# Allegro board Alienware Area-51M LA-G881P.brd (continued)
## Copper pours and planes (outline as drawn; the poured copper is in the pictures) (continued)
UG2_ISL95338_1 on BOTTOM (solid shape): 126.11,143.65 126.11,142.78 126.16,142.73 126.16,142.64 126.27,142.53 126.27,142.1 126.39,141.98 126.39,141.76 126.24,141.61 125.81,141.61 125.77,141.65 125.77,141.81 125.77,141.82 125.77,142.03 125.77,142.03 125.77,142.53 125.87,142.63 125.87,143.62 125.94,143.69 126.07,143.69
UG2_ISL95338_1 on IN4 (solid shape): 122.96,128.17 122.96,127.28 122.9,127.21 120.74,127.21 120.61,127.34 120.61,128.15 120.78,128.32 122.81,128.32
UG2_ISL95338_1 on IN4 (solid shape): 126.58,142.52 126.58,142.11 127.25,141.44 127.25,141.22 126.98,140.94 126.38,140.94 125.82,141.5 125.82,142.55 126,142.73 126.37,142.73
UG2_ISL95338_2 on TOP (solid shape): 147.09,129.44 147.09,128.48 146.96,128.36 146.01,128.36 145.82,128.55 145.82,129.37 146.07,129.63 146.9,129.63
UG2_ISL95338_2 on BOTTOM (solid shape): 148.48,141.1 148.48,140.23 148.54,140.17 148.54,140.11 148.68,139.97 148.68,139.73 148.95,139.46 148.95,139.14 148.87,139.06 148.55,139.06 148.22,139.39 148.22,139.96 148.26,140 148.26,141.1 148.32,141.16 148.42,141.16
UG2_ISL95338_2 on IN4 (solid shape): 146.97,130.38 146.97,128.74 146.65,128.42 145.95,128.42 145.82,128.55 145.82,130.33 145.95,130.45 146.9,130.45
UG2_ISL95338_2 on IN4 (solid shape): 149.88,138.9 149.88,138.33 149.63,138.07 149.31,138.07 148.49,138.9 148.49,139.34 148.11,139.72 148.11,139.91 148.3,140.1 148.68,140.1
UG_3V on TOP (solid shape): 314.5,45.31 314.5,44.5 314.35,44.35 313.56,44.35 313.38,44.52 313.38,45.24 313.59,45.44 314.38,45.44
UG_3V on TOP (solid shape): 327.91,40.33 328.24,40.33 328.32,40.26 328.32,39.52 328.27,39.47 327.96,39.47 327.02,40.41 327.02,40.51 327.25,40.74 327.51,40.74
UG_3V on IN1 (solid shape): 315.29,45.49 315.29,44.65 315.01,44.37 313.82,44.37 313.46,44.73 313.46,45.59 313.54,45.67 315.11,45.67
UG_3V on IN1 (solid shape): 328.14,40.71 328.14,40.21 327.79,39.85 327.43,39.85 325.65,41.63 325.65,41.81 325.86,42.01 326.85,42.01
UG_5V on TOP (solid shape): 317.65,35.46 317.65,34.57 317.55,34.47 316.84,34.47 316.64,34.67 316.64,35.41 316.79,35.56 317.55,35.56
UG_5V on TOP (solid shape): 328.32,37.18 328.32,36.4 327.71,35.79 327.25,35.79 327.13,35.91 327.13,36.07 328.09,37.03 328.09,37.13 328.17,37.21 328.29,37.21
UG_5V on IN1 (solid shape): 318.52,35.35 318.52,34.49 318.36,34.34 317.4,34.34 317.21,34.53 317.21,35.41 317.34,35.53 318.34,35.53
UG_5V on IN1 (solid shape): 328.07,36.47 328.07,36.35 326.62,34.9 326.41,34.9 326.06,35.25 326.06,35.81 326.39,36.14 326.92,36.14 327.46,36.68 327.86,36.68
UG_+1VALWP on TOP (solid shape): 266.37,10.18 266.37,9.95 265.84,9.42 265.65,9.42 265.4,9.68 264.63,9.68 264.57,9.74 264.57,9.93 264.64,10 265.65,10 265.96,10.31 266.24,10.31
UG_+1VALWP on IN1 (solid shape): 266.34,11.48 266.34,9.95 265.79,9.4 265.68,9.4 265.48,9.6 265.48,11.48 265.66,11.66 266.17,11.66
UG_+1VALWP on IN1 (solid shape): 269.21,18.82 269.21,18.31 269.06,18.16 266.95,18.16 266.75,18.36 266.75,18.87 266.93,19.05 268.99,19.05
UG_+1VALWP on TOP: 268.3,19.28 269.16,19.28 269.26,19.17 269.26,18.41 269.14,18.29 268.25,18.29 268.1,18.44 268.1,19.07
UG_CHG on TOP (solid shape): 205.45,139.02 205.45,138.9 205.38,138.83 204.56,138.83 204.37,138.64 204.37,138.39 203.92,137.95 203.61,137.95 203.54,138.01 203.54,138.26 204.37,139.09 205.38,139.09
UG_CHG on BOTTOM (solid shape): 201.08,142.85 201.08,139.96 202.64,138.4 203.68,138.4 204.11,138.83 204.3,138.83 204.43,138.71 204.43,137.8 203.92,137.29 202.15,137.29 199.81,139.63 199.81,142.83 199.94,142.96 200.97,142.96
UG_CHG_R on BOTTOM (solid shape): 200.5,153.76 200.5,152.23 200.31,152.04 199.23,152.04 199.1,152.17 199.1,153.82 199.23,153.95 200.31,153.95
UG_CHG_R on BOTTOM (solid shape): 200.97,146.05 200.97,143.8 200.9,143.72 200.02,143.72 199.9,143.85 199.9,146.07 199.96,146.14 200.89,146.14
UG_CHG_R on IN1 (solid shape): 200.94,146.64 200.94,144.99 200.69,144.74 200.18,144.74 199.93,144.99 199.93,146.64 200.18,146.9 200.69,146.9
UG_CHG_R on IN1 (solid shape): 200.94,153.57 200.94,152.42 200.75,152.23 199.39,152.23 199.07,152.55 199.07,153.63 199.32,153.88 200.63,153.88
UG_VCCSA on IN4 (solid shape): 132.79,114.83 132.79,114.17 132.61,113.99 132.41,113.99 131.14,115.26 131.14,115.49 131.42,115.77 131.85,115.77
UG_VCCSA on IN4 (solid shape): 139.06,116.36 139.06,115.29 138.86,115.09 138.1,115.09 137.95,115.24 137.95,116.3 138.12,116.48 138.94,116.48
UG_VCCSA on BOTTOM: 138.12,117.3 138.79,117.3 139.04,117.04 139.04,116.25 138.86,116.08 138.18,116.08 137.97,116.28 137.97,117.14
UG_VCCSA on BOTTOM: 130.4,115.85 131.42,115.85 132.1,115.16 132.1,114.93 132,114.83 131.77,114.83 131.04,115.57 130.4,115.57 130.3,115.67 130.3,115.75
VCIN_ BATT_TEMP on TOP: 76.39,11.87 76.9,11.87 77.39,11.38 78.36,11.38 78.46,11.28 78.46,10.64 78.22,10.41 78.22,7.17 78.01,6.96 77.05,6.96 76.88,7.13 76.88,10.1 76.33,10.66 76.33,11.81
VDOP_CHG on TOP: 201.42,140.13 202.79,140.13 203.13,140.46 203.5,140.46 203.59,140.38 204.29,140.38 204.39,140.28 205.36,140.28 205.43,140.21 205.43,140.18 205.31,140.05 203.4,140.05 202.74,139.39 201.37,139.39 201.29,139.47 201.29,140
VSB_N_002 on BOTTOM (solid shape): 58.44,22.22 58.44,21.64 58.52,21.56 60.05,21.56 60.2,21.41 60.2,20.9 60.05,20.75 58.65,20.75 58.39,20.5 58.39,19.48 58.19,19.28 57.71,19.28 57.58,19.4 57.58,20.29 57.81,20.52 57.81,22.17 57.89,22.25 58.42,22.25
N16550351 on TOP (solid shape): 195.86,151.53 195.86,148.3 198.02,146.14 198.02,141.68 197.75,141.41 197.75,139.41 197.64,139.3 196.4,139.3 196.4,142.68 195.63,142.68 195.63,139.3 194.95,139.3 193.38,137.73 193.38,134.14 193.26,134.01 191.79,134.01 191.67,134.14 191.67,138.96 191.99,139.28 191.99,142.26 192.18,142.45 193.19,142.45 193.64,142.9 193.64,144.68 193,145.31 190.78,145.31 189.89,146.2 189.89,151.72 190.33,152.17 195.22,152.17
N16606246 on TOP (solid shape): outline of 103 points within 130,129.83 140.28,143.89
N16606246 on BOTTOM (solid shape): 132.71,143.84 133.96,143.84 135.79,142.01 137.44,142.01 137.92,141.53 137.92,136.45 137.38,135.91 137.38,129.89 136.49,129 132.45,129 132.36,129.1 132.36,135.3 131.94,135.72 129.27,135.72 129.22,136.05 128.91,136.19 128.91,138.22 129.06,138.36 129.82,138.36 130,138.54 130,142.28 130.27,142.55 130.27,143.96 130.43,144.12 132.44,144.12
N16611457 on TOP: 118.33,150.58 118.79,150.12 118.79,145.03 118.36,144.6 109.07,144.6 108.04,145.63 105.56,145.63 105.31,145.88 105.31,148.42 105.5,148.61 107.91,148.61 108.42,149.12 108.42,153.02 107.93,153.5 107.93,155.31 108.25,155.62 111.21,155.62 111.38,155.45 111.38,153.73 111.8,153.31 111.8,149.55 111.84,149.51 113.16,149.51 114.23,150.58
N16611457 on BOTTOM: 116.33,155.22 117.25,155.22 119.4,153.06 119.4,146.33 119.21,146.14 109.31,146.14 108.43,145.26 105.69,145.26 105.56,145.39 105.56,152.17 110.01,156.61 114.93,156.61
N16639315 on BOTTOM (solid shape): outline of 179 points within 112.55,168.08 116.25,172.27
N16690790 on TOP (solid shape): 205.48,159.77 205.48,156.07 205.47,156.07 205.47,154.67 205.22,154.41 201.88,154.41 201.44,154.85 201.44,157.66 201.21,157.89 194.73,157.89 194.53,157.69 194.53,155.34 192.17,152.99 185.38,152.99 185.25,153.12 185.25,155.9 185.53,156.18 188.45,156.18 192.27,160 205.24,160
N16690790 on BOTTOM (solid shape): 205.37,159.94 205.37,154.94 204.91,154.48 199.95,154.48 199.81,154.62 199.81,157.66 199.56,157.92 194.03,157.92 193.9,157.79 193.9,155.32 193.66,155.08 190.59,155.08 190.43,155.24 190.43,158.56 192.35,160.47 204.84,160.47
N16690790 on IN2 (solid shape): 205.46,160.1 205.46,154.72 205.22,154.48 200.16,154.48 200.03,154.6 200.03,156.86 199.59,157.3 194.24,157.3 193.9,156.97 193.9,155.32 193.66,155.08 191.88,155.08 191.61,155.35 191.61,159.76 192.32,160.47 205.09,160.47
N16690790 on IN3 (solid shape): 205.46,160.1 205.46,154.72 205.22,154.48 200.16,154.48 200.03,154.6 200.03,156.86 199.59,157.3 194.24,157.3 193.9,156.97 193.9,155.32 193.66,155.08 191.88,155.08 191.61,155.35 191.61,159.76 192.32,160.47 205.09,160.47
N16716198 on TOP (solid shape): 206.02,131.32 206.02,128.62 205.64,128.24 204.77,128.24 204.39,128.62 204.39,130.15 204.22,130.33 204.22,131.37 204.34,131.49 205.84,131.49
N16781018 on TOP (solid shape): 135.43,122.09 135.43,120.72 136,120.15 139.98,120.15 140.1,120.04 140.1,118.36 139.81,118.07 134.89,118.07 134.62,118.35 134.62,122.08 134.64,122.11 135.41,122.11
N16781018 on BOTTOM: 135.6,120.06 137.82,120.06 138.07,120.32 138.07,121.44 138.18,121.54 140.26,121.54 140.56,121.23 140.56,116.84 140.48,116.76 139.72,116.76 139.45,117.04 139.45,117.38 139.02,117.8 138.07,117.8 137.92,117.96 135.79,117.96 135.35,118.4 135.35,119.81
N16782292 on BOTTOM (solid shape): 148.93,122.17 148.93,119.59 148.87,119.53 147.57,119.53 147.45,119.66 147.45,120.29 147.79,120.64 147.79,122.18 147.88,122.27 148.83,122.27
N16829365 on TOP: 77.15,14.17 76.31,14.17 76.19,14.05 76.19,12.96 77.23,11.91 79.31,11.91 79.41,12.02 79.41,12.87 79.36,12.92 78.8,12.92 78.67,12.8 77.83,12.8 77.53,13.1 77.53,13.78
N16862697 on TOP: 108.48,33.11 110.07,33.11 110.2,32.98 110.2,30.95 109.88,30.63 109.05,30.63 108.8,30.88 108.8,31.65 108.42,32.03 108.42,33.04
N16862746 on BOTTOM: 100.55,35.08 101.18,35.08 101.24,35.01 101.24,32.98 101.18,32.92 100.55,32.92 100.48,32.98 100.48,35.01
N16862747 on BOTTOM: 102.01,35.14 102.83,35.14 102.89,35.2 104.16,35.2 104.29,35.08 104.29,34.95 104.23,34.88 103.53,34.88 103.15,34.5 102.96,34.5 102.64,34.19 101.94,34.19 101.88,34.25 101.88,35.01
N16862749 on BOTTOM: 101.94,34.06 102.77,34.06 102.96,34.25 104.16,34.25 104.29,34.12 104.29,33.93 104.23,33.87 103.4,33.87 103.28,33.74 102.96,33.74 102.64,33.42 102.64,32.98 102.58,32.92 101.94,32.92 101.88,32.98 101.88,34
N16862811 on BOTTOM: 100.55,26.06 101.18,26.06 101.24,25.99 101.24,24.03 101.18,23.96 100.55,23.96 100.48,24.03 100.48,25.99
N16862814 on BOTTOM: 101.94,24.85 102.51,24.85 102.76,25.1 102.76,25.18 102.94,25.36 103.22,25.36 103.34,25.23 104.42,25.23 104.48,25.17 104.48,24.98 104.42,24.92 103.47,24.92 102.77,24.22 102.77,24.09 102.64,23.96 101.94,23.96 101.88,24.03 101.88,24.79
N16862815 on BOTTOM: 101.94,26.12 102.64,26.12 102.77,26.25 104.48,26.25 104.55,26.19 104.55,25.99 104.48,25.93 103.66,25.93 103.24,25.51 102.92,25.51 102.58,25.17 101.94,25.17 101.88,25.23 101.88,26.06
N16868041 on BOTTOM: 116.23,65.87 116.93,65.87 117.06,65.75 117.06,63.27 116.67,62.89 113.94,62.89 113.88,62.95 113.88,63.9 114.01,64.03 115.66,64.03 116.17,64.54 116.17,65.81
N16868085 on BOTTOM (solid shape): 104.8,62.13 104.8,59.97 104.74,59.9 104.16,59.9 104.04,60.03 104.04,62.13 104.1,62.19 104.74,62.19
N16868091 on BOTTOM (solid shape): 106.9,60.73 107.72,60.73 107.78,60.67 107.78,60.48 107.72,60.41 106.39,60.41 106.2,60.22 106.2,60.03 106.13,59.97 105.5,59.97 105.43,60.03 105.43,60.86 105.5,60.92 106.7,60.92
N16868093 on BOTTOM (solid shape): 106.64,61.75 107.66,61.75 107.78,61.62 107.78,61.43 107.72,61.36 106.39,61.36 106.2,61.17 105.56,61.17 105.5,61.24 105.5,62.13 105.56,62.19 106.2,62.19
N16872727 on TOP: 118.26,77.68 119.28,77.68 119.4,77.56 119.4,75.91 119.15,75.65 117.56,75.65 117.44,75.78 117.44,76.86
N16872751 on BOTTOM (solid shape): 106.68,73.84 106.68,71.75 106.63,71.7 105.99,71.7 105.92,71.78 105.92,73.81 105.99,73.89 106.63,73.89
N16872754 on BOTTOM (solid shape): 108.31,72.36 108.69,72.36 109.12,71.93 109.8,71.93 109.88,71.85 109.88,71.7 109.8,71.63 108.84,71.63 108.58,71.37 108.58,71 108.37,70.79 108.09,70.79 107.31,71.56 107.31,72.57 107.37,72.62 108.05,72.62
N16872755 on BOTTOM (solid shape): 109.02,72.92 109.83,72.92 109.91,72.85 109.91,72.72 109.8,72.62 108.38,72.62 108.05,72.95 107.37,72.95 107.29,73.02 107.29,73.76 107.42,73.89 108.05,73.89
N16876699 on TOP: 107.4,41.11 108.04,41.11 108.23,41.3 110.01,41.3 110.2,41.11 110.2,40.22 110.01,40.03 107.4,40.03 107.28,40.16 107.28,40.98
N16876717 on BOTTOM: 101.37,44.92 101.5,44.79 101.5,42.89 101.37,42.76 100.74,42.76 100.61,42.89 100.61,43.81 99.82,44.6 99.82,44.84 99.89,44.92
N16876720 on BOTTOM: 102.13,43.71 103.15,43.71 103.4,43.46 104.29,43.46 104.36,43.39 104.36,43.2 104.29,43.14 103.09,43.14 102.7,42.76 102.07,42.76 102.01,42.82 102.01,43.58
N16876721 on BOTTOM: 102.07,44.92 102.89,44.92 103.4,44.41 104.23,44.41 104.29,44.35 104.29,44.22 104.23,44.16 103.02,44.16 102.89,44.03 102.07,44.03 102.01,44.09 102.01,44.85
N16876814 on BOTTOM: 114.45,54.82 113.18,53.55 111.4,53.55 111.34,53.62 111.34,54.44 111.47,54.57 113.25,54.57 113.63,54.95 113.63,56.66 113.79,56.83 114.33,56.83 114.45,56.71
N16876832 on BOTTOM: 102.32,53.68 102.83,53.68 102.96,53.55 102.96,51.59 102.89,51.52 102.32,51.52 102.2,51.65 102.2,53.55
N16876835 on BOTTOM: 103.66,52.41 104.29,52.41 104.86,51.84 105.63,51.84 105.75,51.71 105.75,51.52 105.69,51.46 103.66,51.46 103.59,51.52 103.59,52.35
N16876836 on BOTTOM: 103.66,53.68 104.29,53.68 104.36,53.62 104.36,53.3 104.8,52.86 105.69,52.86 105.82,52.73 105.82,52.54 105.75,52.47 104.48,52.47 104.29,52.66 103.72,52.66 103.59,52.79 103.59,53.62
N16880234 on BOTTOM: 161,17.87 161.57,17.87 162.33,17.1 162.33,14.95 162.2,14.82 161.31,14.82 161.19,14.95 161.19,16.66 160.87,16.98 160.87,17.74
N16880256 on BOTTOM: 136.11,15.2 138.14,15.2 138.26,15.07 138.26,14.25 138.14,14.12 137.44,14.12 137.18,13.87 137.18,13.42 137.12,13.36 136.11,13.36 135.98,13.49 135.98,15.07
N16880500 on BOTTOM: 145.64,12.09 147.7,12.09 147.8,11.99 147.8,11.4 147.75,11.35 145.64,11.35 145.59,11.4 145.59,12.04
N16884080 on BOTTOM: 125.5,11.9 127.53,11.9 127.6,11.83 127.6,11.26 127.47,11.14 125.5,11.14 125.37,11.26 125.37,11.77
N16884081 on BOTTOM: 127.66,14.76 127.85,14.76 127.91,14.69 127.91,13.87 127.72,13.68 127.72,12.79 127.53,12.6 126.71,12.6 126.64,12.66 126.64,13.23 126.9,13.49 127.15,13.49 127.6,13.93 127.6,14.69
N16884082 on BOTTOM: 126.71,14.69 126.83,14.69 126.9,14.63 126.9,13.8 126.39,13.29 126.39,12.66 126.33,12.6 125.44,12.6 125.37,12.66 125.37,13.36 125.56,13.55 126.2,13.55 126.58,13.93 126.58,14.56
N17623308 on TOP (solid shape): 202.43,165.4 202.43,162.66 202.28,162.51 201.72,162.51 201.51,162.71 201.51,165.33 201.79,165.61 202.23,165.61
N17623308 on TOP (solid shape): 206.29,165.4 206.29,162.66 206.14,162.51 205.58,162.51 205.38,162.71 205.38,165.33 205.66,165.61 206.09,165.61
N17623308 on TOP (solid shape): 210.07,165.4 210.07,162.66 209.92,162.51 209.36,162.51 209.16,162.71 209.16,165.33 209.44,165.61 209.87,165.61
N17623308 on TOP (solid shape): 198.64,165.4 198.64,162.66 198.49,162.51 198.06,162.51 197.95,162.62 197.95,162.98 197.73,163.19 197.73,165.33 198.01,165.61 198.44,165.61
N17623308 on BOTTOM: 198.09,164.23 209.29,164.23 209.92,163.6 209.92,162.53 209.69,162.3 197.2,162.3 197.13,162.38 197.13,163.27
N20453798 on TOP: 151.68,148.25 151.68,147.14 151.89,146.93 152.97,146.93 153.16,147.12 153.16,147.62 153.39,147.85 153.9,147.85 153.97,147.92 153.97,148.42 153.89,148.49 152.61,148.49 152.46,148.34 151.77,148.34
N20466818 on TOP (solid shape): 114.02,140.51 114.02,138.71 113.84,138.53 113.08,138.53 112.92,138.69 112.92,139.02 112.29,139.65 112.29,140.54 112.37,140.61 113.92,140.61
N20469265 on TOP (solid shape): 150.95,138.63 151.99,138.63 152.07,138.55 152.07,137.95 151.94,137.82 150.49,137.82 150.16,137.49 149,137.49 148.92,137.56 148.92,138.94 149.15,139.16 150.42,139.16
N20478252 on BOTTOM: 240.25,15.01 240.25,14.37 240.37,14.25 240.37,12.53 240.5,12.41 241.2,12.41 241.52,12.72 241.52,13.8 242.02,14.31 242.28,14.31 242.34,14.37 242.34,15.01 242.15,15.2 240.44,15.2
N20591895 on BOTTOM: 375.62,49.46 377.15,49.46 378.54,50.84 378.54,53.17 378.71,53.34 379.21,53.34 379.39,53.17 379.39,48.41 378.8,47.83 376.94,47.83 376.15,48.63 375.58,48.63 375.49,48.71 375.49,49.33
N20980290 on TOP: 171.08,167.68 171.03,167.62 171.03,166.63 171.19,166.46 172.03,166.46 172.29,166.2 172.29,165.31 172.35,165.25 172.49,165.25 172.57,165.32 172.57,166.15 172.65,166.23 173.21,166.23 173.29,166.32 173.29,166.5 173.5,166.71 173.5,167.64 173.47,167.68
N20994075 on TOP: 163.53,162.67 164.19,162.67 164.72,162.14 164.72,161.08 164.89,160.91 165.98,160.91 166.11,161.03 166.11,164.14 166.06,164.19 165.1,164.19 165.03,164.12 165.03,163.13 164.85,162.95 164.26,162.95 164.21,163 163.53,163 163.46,162.94 163.46,162.74
N21000962 on TOP (solid shape): 193.23,163.41 193.23,162.33 193.49,162.07 193.8,162.07 193.98,162.25 193.98,162.98 194.06,163.06 194.22,163.06 194.3,162.98 194.3,161.72 193.61,161.04 192.08,161.04 192.03,161.09 192.03,163.44 192.07,163.48 193.16,163.48
N22717170 on TOP: 156.14,149.47 156.96,149.47 157.38,149.88 159.06,149.88 160.48,151.31 161.37,151.31 161.38,151.3 161.82,151.3 161.88,151.37 161.88,152.15 161.73,152.29 159.47,152.29 158.56,153.2 158.56,154.54 158.29,154.81 157.4,154.81 157.21,154.62 157.21,151.1 157.11,151 156.19,151 156.09,150.9 156.09,149.52
N22744293 on BOTTOM: 145.38,162.08 143.74,162.08 142.04,160.38 142.04,159.45 142.28,159.2 142.99,159.2 143.38,158.81 144.94,158.81 145.72,159.59 146.96,159.59 147.23,159.86 147.23,161.43 146.99,161.67 145.79,161.67
N22932271 on TOP: 123.78,152.85 124.6,152.85 125.58,153.83 125.58,154.66 125.5,154.74 124.93,154.74 124.43,154.24 123.77,154.24 123.66,154.13 123.66,152.97
N22943835 on BOTTOM: 147.94,167.48 147.94,166.84 148.07,166.7 149.75,166.7 149.81,166.76 149.81,168.41 149.67,168.54 148.79,168.54 148.73,168.48 148.73,167.71 148.57,167.55 148.01,167.55
N22957086 on BOTTOM: 148.95,170.76 148.95,170.05 149.05,169.95 150.95,169.95 151.01,170.01 151.01,170.79 150.93,170.87 149.06,170.87
N22958603 on BOTTOM (solid shape): 129.29,131.81 129.29,130.65 129.1,130.46 127.41,130.46 127.02,130.07 126.4,130.07 126.3,130.17 126.3,131.49 126.41,131.6 128.2,131.6 128.54,131.94 129.16,131.94
N24139767 on TOP (solid shape): 268.13,69.73 268.13,68.17 268.04,67.97 268.13,67.76 268.13,64.97 267.79,64.64 267.79,64.24 268.61,63.42 268.84,63.42 268.88,63.41 269.05,63.24 269.24,63.24 269.34,63.14 269.34,62.88 269.34,62.87 269.22,62.85 269.13,62.79 269.02,62.79 269.02,62.82 268.82,63.01 268.78,63.01 268.77,63.02 268.45,63.02 267.23,64.24 267.23,67.57 266.6,68.2 266.6,69.81 266.65,69.86 268,69.86
N24654525 on TOP: 276.7,86.23 273.74,86.23 273.59,86.38 273.59,87.27 274.03,87.27 274.1,87.34 274.1,88.67 274.03,88.73 273.71,88.73 273.59,88.86 273.59,89.3 274.41,90.13 276.06,90.13 276.76,89.43 276.76,88.42 277.02,88.16 277.02,86.55
N25473625 on BOTTOM: 86.51,18.82 86.51,18.18 86.77,17.93 88.61,17.93 89.31,17.23 90.19,17.23 90.39,17.42 90.39,18.57 90.19,18.76 88.99,18.76 88.86,18.88 86.58,18.88
N25489388 on BOTTOM: 164.48,176.56 164.48,174.43 164.69,174.22 165.8,174.22 165.92,174.34 165.92,177.23 165.57,177.57 164.37,177.57 164.24,177.44 164.24,176.81
N28714782 on BOTTOM: 190.66,152.3 190.66,154.61 190.73,154.68 192.65,154.68 192.86,154.46 192.86,152.3 192.68,152.12 190.84,152.12
N28714793 on TOP (solid shape): 193.26,144.23 193.26,143.03 193.13,142.9 192.18,142.9 191.99,143.09 191.99,144.23 192.18,144.42 193.06,144.42
N28714793 on TOP (solid shape): 202.84,136.99 202.84,135.91 202.72,135.78 201.61,135.78 201.54,135.84 201.54,136.96 201.64,137.06 202.78,137.06
N28714793 on BOTTOM (solid shape): 193.27,144.57 193.27,142.95 193.22,142.9 192.24,142.9 192.05,143.09 192.05,144.1 192.05,144.11 192.05,144.62 192.13,144.69 193.14,144.69
N28714793 on IN1 (solid shape): 202.84,136.93 202.84,136.17 202.65,135.98 201.45,135.98 201.32,136.1 201.32,136.87 201.45,136.99 202.78,136.99
N28714793 on IN1: 191.6,144.42 191.6,142.07 191.86,141.82 193.13,141.82 193.32,142.01 193.32,144.36 193.13,144.55 191.73,144.55
N38701284 on TOP (solid shape): 355.96,30.91 355.96,28.7 355.7,28.45 355.7,26.36 355.02,25.68 354.15,25.68 353.97,25.86 353.97,26.97 354.2,27.2 354.38,27.2 354.66,27.48 354.66,28.01 354.66,28.02 354.66,28.35 355.65,29.34 355.65,30.88 355.71,30.94 355.93,30.94

Small or netless copper shapes (teardrops, artwork), in the pictures only: 118 on TOP, 29 on BOTTOM

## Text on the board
Ref Des/Silkscreen Bottom: H42 | H70 | H63 | H60 | H56 | H58 | H59 | H57 | SSD-2(PCle+SATA) | 4 | 2 | 3 | 1 | DDR4 ONLY - DIMM4 | DDR4 ONLY - DIMM2 | DDR4 ONLY - DIMM3 | DDR4 ONLY - DIMM1 | DIMM1->DIMM2->DIMM3->DIMM4 | Memory population order
User.Comments: CR_BGA_96P_1 | CR_GPU_1 | LA-G881P | Minjia_Cai | 2019-11-19 | 2018-11-19 | DDQ70 | 1.0(A00)
Ref Des/Silkscreen Top: B | JDGFF2 | JDGFF1 | A
GND4: GND4
COMPVAL_TYPE_TOP: L7 | L8 | GND2 | BOT
User.40: trace Width | Width/space | L4/L7 | L7/L9 | L2/L4 | L2 | L9 | 6.8mil | 8.8 mil | 8.5mil | 5.3mil | 5.3 mil | 6.9 mil | 4.8 mil | 5.9mil | 6.2mil | 4.4 mil | 3.3 mil | 4.1mil | 4.4mil | 6.2 / 4 | 6.5 / 4.5 | 5.8 /4 | 6.8 / 4 | 3.3 / 3.3 | 4.4 / 4.3 | 4.7 / 7.3 | 4 / 8 | 3.3 / 12 | 3.5 / 9 | 1_6mm-10L(PP1080,PP2116,PP7628x3)_180420.pdf | L1-TOP | L2-GND1 | L3-IN1 | L4-GND2 | L5-IN2 | L6-IN3 | L7-GND3 | L8-IN4 | L9-GND4 | L10-BOT | LAYER | NAME | STACKUP:10 LAYER | 34 ohm | 40 ohm | THICKNESS=1.6mm | 42 ohm | 50 ohm | 66 ohm | 68 ohm | 85 ohm | 90 ohm | 100 ohm | Ref
User.45: FIGURE | SIZE | 8.0 | 20.0 | 28.0 | 30.0 | 35.0 | 36.0 | 39.0 | 47.0 | 90.0 | 118.0 | 126.0 | 130.0 | 150.0 | 26.0 | 43.0 | 63.0 | 106.0 | 49.0x28.0 | 55.0x28.0 | 67.0x24.0 | 67.0x28.0 | 69.0x20.0 | 75.0x24.0 | 75.0x28.0 | 79.0x35.0 | 94.0x24.0 | 94.0x28.0 | 33.0x26.0 | 157.0x118.0 | DRILL CHART: TOP to BOTTOM | ALL UNITS ARE IN MILS | TOLERANCE | +3.0/-3.0 | +2.0/-2.0 | PLATED | NON-PLATED | QTY | 9393 | 33 | 18 | 1 | 8 | 9 | 5 | 13 | 4 | 2 | 7
